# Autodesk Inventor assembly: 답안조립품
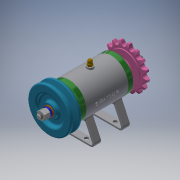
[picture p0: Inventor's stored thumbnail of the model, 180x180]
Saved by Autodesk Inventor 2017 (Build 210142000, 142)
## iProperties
Part Number: 답안조립품
Material: 일반
Document SubType Name: Assembly
Designer: Administrator
Author: Administrator
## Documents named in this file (16)
- C:\Users\Administrator\Desktop\711206V1022\답안조립품.iam
- C:\Users\Administrator\Desktop\711206V1022\본체.ipt
- C:\Users\Administrator\Desktop\711206V1022\베어링 6002.ipt
- C:\Users\Administrator\Desktop\711206V1022\축.ipt
- C:\Users\Administrator\Desktop\711206V1022\커버.ipt
- C:\Users\Administrator\Desktop\711206V1022\볼트 M4 x 12.ipt
- C:\Users\Administrator\Desktop\711206V1022\스프로킷.ipt
- C:\Users\Administrator\Desktop\711206V1022\키 3 x 3.ipt
- C:\Users\Administrator\Desktop\711206V1022\스프링와셔 8.ipt
- C:\Users\Administrator\Desktop\711206V1022\와셔 8 x 17.ipt
- C:\Users\Administrator\Desktop\711206V1022\너트 M8.ipt
- C:\Users\Administrator\Desktop\711206V1022\니플 M6 x 0.75.ipt
- C:\Users\Administrator\Desktop\711206V1022\오일 실 15 x 25 x 7.ipt
- C:\Users\Administrator\Desktop\711206V1022\V벨트풀리.ipt
- C:\Users\Administrator\Desktop\711206V1022\볼트 M6 x 8.ipt
- C:\Users\Administrator\Desktop\711206V1022\와셔 6 x 11.5.ipt
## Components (11 placed, 3 different names)
1. KS B 2023 6002 - 15 x 32 x 9:1
2. KS B 2023 6002 - 15 x 32 x 9:2
3. V벨트풀리:1
4. ISO 4762 M4 x 12:1
5. ISO 4762 M4 x 12:2
6. ISO 4762 M4 x 12:3
7. ISO 4762 M4 x 12:4
8. ISO 4762 M4 x 12:5
9. ISO 4762 M4 x 12:6
10. ISO 4762 M4 x 12:7
11. ISO 4762 M4 x 12:8
